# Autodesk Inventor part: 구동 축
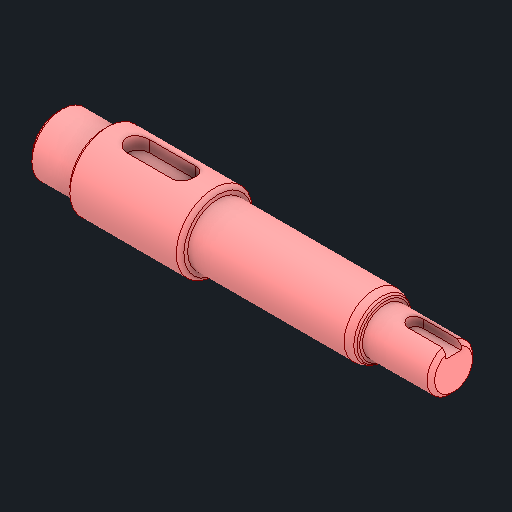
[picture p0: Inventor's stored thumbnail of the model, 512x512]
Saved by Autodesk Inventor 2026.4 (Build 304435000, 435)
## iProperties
Created: 2026-09
Part Number: 구동 축
Material: 강철, 탄소
Document SubType Name: Modeling
Designer: user
Density: 7.85 g/cm^3
Appearance: 기본값
Author: jhkim
Sending System: Autodesk Inventor 2027
Preprocessor: ST-DEVELOPER v20.1
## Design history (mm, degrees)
feature "솔리드1"
node "솔리드2"
